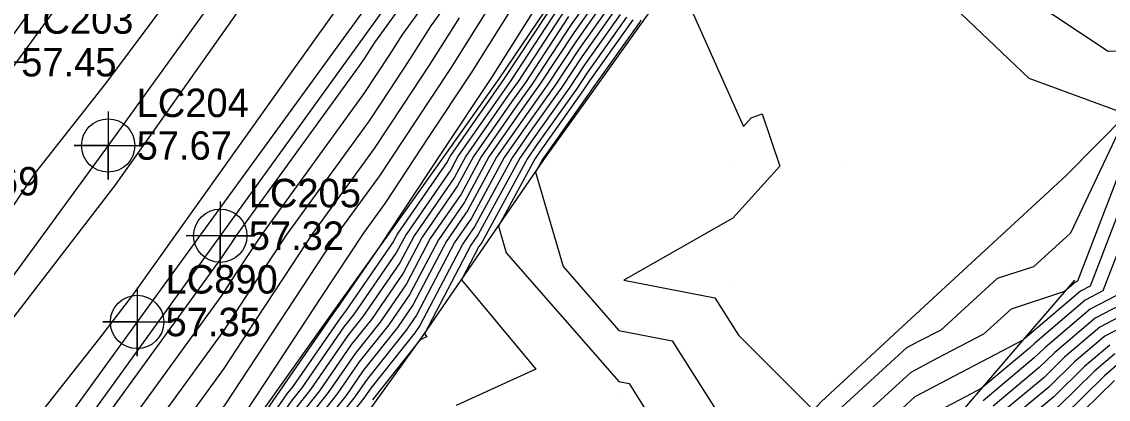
# Model space of a CAD drawing. Extents: x 2188792 to 2191981, y 386090 to 389710.
# Drawn here: x 2190227.7 to 2190323.1, y 387729.7 to 387762.9 of the extents above; entities that cross this region are included whole.
import ezdxf

# ---------------------------------------------------------------- set-up
doc = ezdxf.new("R2010")
doc.units = 0
for name, color, linetype in [('DTM Contours Major', 7, 'Continuous'), ('DTM Contours Minor', 7, 'Continuous'), ('Exist DTM QL2 LIDAR Elevation Point', 7, 'Continuous'), ('Exist Roads EOP', 7, 'Continuous'), ('Exist Roads EOP Cogo Elevation', 7, 'Continuous'), ('Exist Roads EOP Cogo Number', 7, 'Continuous'), ('Exist Roads EOP Cogo Point CELL', 7, 'Continuous'), ('Exist Roads EOT', 7, 'Continuous'), ('Exist Roads EOT Cogo Elevation', 7, 'Continuous'), ('Exist Roads EOT Cogo Number', 7, 'Continuous'), ('Exist Roads EOT Cogo Point CELL', 7, 'Continuous'), ('PH Exist DTM Breakline', 7, 'Continuous')]:
    doc.layers.add(name, color=color, linetype=linetype)

msp = doc.modelspace()

# ---------------------------------------------------------------- linework, layer by layer
at = {"layer": 'DTM Contours Major'}
for points in [[(2190218.456, 387701.786), (2190227.964, 387714.893), (2190229.45, 387716.967), (2190230.892, 387718.979), (2190232.292, 387720.934), (2190245.286, 387738.846), (2190246.51, 387740.711), (2190247.67, 387742.479), (2190248.772, 387744.157), (2190257.784, 387756.577), (2190258.921, 387758.299), (2190260.004, 387759.938), (2190261.168, 387761.785), (2190274.661, 387780.393)], [(2190307.217, 387766.453), (2190316.134, 387757.911), (2190324.761, 387754.756), (2190319.81, 387744.296), (2190316.542, 387741.341), (2190313.357, 387740.301), (2190308.401, 387735.783), (2190306.457, 387734.761), (2190305.402, 387734.206), (2190299.411, 387728.718)], [(2190273.614, 387765.399), (2190268.942, 387757.989), (2190264.596, 387751.41), (2190260.031, 387744.499), (2190259.974, 387744.419), (2190259.136, 387743.142), (2190255.371, 387737.676), (2190255.314, 387737.604), (2190250.727, 387730.957), (2190250.605, 387730.803), (2190246.088, 387724.269), (2190245.908, 387724.041), (2190240.646, 387716.891), (2190240.388, 387716.558), (2190235.157, 387709.453), (2190234.868, 387709.08), (2190229.666, 387702.018), (2190229.348, 387701.607), (2190224.174, 387694.584)], [(2190277.438, 387764.713), (2190275.953, 387762.619), (2190272.566, 387757.461), (2190271.045, 387755.317), (2190268.058, 387751.015), (2190266.278, 387747.733), (2190263.58, 387743.833), (2190261.496, 387739.855), (2190259.171, 387736.479), (2190257.006, 387733.762), (2190254.62, 387730.304), (2190252.504, 387727.63), (2190250.063, 387724.099), (2190247.992, 387721.466), (2190245.052, 387717.47), (2190242.494, 387714.178), (2190239.504, 387710.117), (2190236.995, 387706.883), (2190233.959, 387702.761), (2190231.494, 387699.58), (2190228.416, 387695.401), (2190225.994, 387692.271)], [(2190280.252, 387763.524), (2190277.109, 387759.091), (2190275.766, 387757.046), (2190272.603, 387752.586), (2190271.427, 387750.893), (2190267.794, 387744.19), (2190267.137, 387743.242), (2190263.055, 387735.449), (2190263.267, 387735.195), (2190263.041, 387735.091), (2190262.644, 387734.871), (2190258.699, 387729.92), (2190258.513, 387729.65)], [(2190324.892, 387738.359), (2190321.961, 387736.832), (2190318.412, 387733.813), (2190317.049, 387732.476), (2190313.019, 387729.104)], [(2190324.111, 387732.888), (2190322.78, 387731.756), (2190319.174, 387728.221), (2190317.482, 387726.805), (2190314.246, 387723.658), (2190312.152, 387721.939), (2190309.328, 387719.218), (2190307.187, 387716.235), (2190304.187, 387712.287), (2190302.104, 387709.386), (2190299.023, 387705.335), (2190296.998, 387702.517), (2190296.445, 387700.171), (2190293.815, 387695.062), (2190291.908, 387692.794), (2190289.248, 387687.115), (2190288.634, 387685.669), (2190285.479, 387681.106), (2190282.146, 387676.285), (2190281.697, 387675.341), (2190278.212, 387670.363), (2190277.906, 387669.746), (2190273.071, 387663.513)]]:
    msp.add_lwpolyline(points, dxfattribs=at)
at = {"layer": 'DTM Contours Minor'}
for points in [[(2190274.614, 387783.039), (2190258.679, 387761.062), (2190258.216, 387760.328), (2190257.786, 387759.677), (2190257.334, 387758.992), (2190246.531, 387744.104), (2190246.108, 387743.459), (2190245.662, 387742.78), (2190245.192, 387742.064), (2190229.327, 387720.193), (2190228.805, 387719.465), (2190228.268, 387718.715), (2190227.714, 387717.942), (2190215.973, 387701.758)], [(2190219.575, 387716.076), (2190234.549, 387735.079), (2190237.443, 387738.838), (2190249.235, 387755.366), (2190251.15, 387758.09), (2190265.367, 387778.02)], [(2190220.939, 387701.815), (2190228.214, 387711.844), (2190230.632, 387715.219), (2190232.978, 387718.494), (2190235.256, 387721.674), (2190245.379, 387735.629), (2190247.357, 387738.642), (2190249.232, 387741.498), (2190251.012, 387744.209), (2190258.233, 387754.161), (2190260.056, 387756.921), (2190261.792, 387759.549), (2190263.657, 387762.508), (2190274.708, 387777.747)], [(2190243.271, 387768.482), (2190235.055, 387757.448), (2190228.888, 387749.601), (2190217.395, 387732.559), (2190214.432, 387727.547), (2190204.397, 387712.818), (2190202.052, 387708.946), (2190187.254, 387685.834), (2190204.7, 387708.079), (2190206.378, 387710.213), (2190218.002, 387725.342), (2190221.117, 387729.294), (2190235.868, 387748.461), (2190239.037, 387752.903), (2190247.964, 387765.605)], [(2190313.388, 387766.775), (2190323.109, 387760.3), (2190329.813, 387760.503)], [(2190275.029, 387765.442), (2190270.006, 387757.793), (2190269.799, 387757.501), (2190265.363, 387751.114), (2190265.066, 387750.567), (2190260.734, 387744.307), (2190260.328, 387743.532), (2190256.131, 387737.437), (2190255.652, 387736.836), (2190251.505, 387730.826), (2190250.985, 387730.169), (2190246.883, 387724.235), (2190246.325, 387723.526), (2190241.527, 387717.007), (2190240.809, 387716.082), (2190236.026, 387709.586), (2190235.293, 387708.641), (2190230.525, 387702.166), (2190229.777, 387701.202), (2190225.022, 387694.748)], [(2190271.125, 387764.676), (2190267.154, 387758.379), (2190263.461, 387752.788), (2190259.582, 387746.914), (2190257.733, 387744.367), (2190253.919, 387738.556), (2190249.9, 387732.434), (2190245.661, 387725.977), (2190244.151, 387723.895), (2190239.238, 387717.038), (2190234.179, 387709.975), (2190228.965, 387702.697), (2190228.387, 387701.9), (2190223.206, 387694.664)], [(2190275.26, 387764.736), (2190270.646, 387757.71), (2190270.111, 387756.955), (2190266.037, 387751.089), (2190265.369, 387749.858), (2190261.446, 387744.188), (2190260.62, 387742.612), (2190256.891, 387737.198), (2190255.991, 387736.067), (2190252.284, 387730.696), (2190251.365, 387729.534), (2190247.678, 387724.201), (2190246.742, 387723.011), (2190242.409, 387717.123), (2190241.23, 387715.606), (2190236.896, 387709.719), (2190235.718, 387708.201), (2190231.383, 387702.315), (2190230.207, 387700.796), (2190225.87, 387694.911)], [(2190225.904, 387701.872), (2190228.715, 387705.746), (2190232.996, 387711.723), (2190237.152, 387717.523), (2190241.186, 387723.155), (2190245.567, 387729.195), (2190249.053, 387734.504), (2190252.356, 387739.537), (2190255.493, 387744.314), (2190259.132, 387749.33), (2190262.326, 387754.166), (2190265.367, 387758.769), (2190268.636, 387763.953)], [(2190278.001, 387764.475), (2190276.184, 387761.914), (2190273.206, 387757.378), (2190271.357, 387754.77), (2190268.732, 387750.991), (2190266.581, 387747.024), (2190264.292, 387743.715), (2190261.788, 387738.936), (2190259.931, 387736.24), (2190257.345, 387732.993), (2190255.398, 387730.173), (2190252.884, 387726.996), (2190250.858, 387724.065), (2190248.409, 387720.951), (2190245.933, 387717.586), (2190242.915, 387713.703), (2190240.373, 387710.25), (2190237.42, 387706.443), (2190234.817, 387702.909), (2190231.924, 387699.175), (2190229.264, 387695.565), (2190226.426, 387691.898)], [(2190275.491, 387764.031), (2190271.286, 387757.627), (2190270.422, 387756.409), (2190266.71, 387751.064), (2190265.672, 387749.15), (2190262.157, 387744.07), (2190260.912, 387741.693), (2190257.651, 387736.958), (2190256.329, 387735.299), (2190253.063, 387730.565), (2190251.745, 387728.899), (2190248.473, 387724.167), (2190247.159, 387722.496), (2190243.29, 387717.238), (2190241.651, 387715.13), (2190237.765, 387709.852), (2190236.144, 387707.762), (2190232.242, 387702.464), (2190230.636, 387700.391), (2190226.719, 387695.074)], [(2190278.563, 387764.238), (2190276.415, 387761.208), (2190273.846, 387757.295), (2190271.668, 387754.224), (2190269.406, 387750.966), (2190266.884, 387746.316), (2190265.003, 387743.597), (2190262.08, 387738.017), (2190260.691, 387736.001), (2190257.683, 387732.225), (2190256.177, 387730.042), (2190253.264, 387726.361), (2190251.653, 387724.031), (2190248.826, 387720.436), (2190246.814, 387717.702), (2190243.337, 387713.227), (2190241.243, 387710.383), (2190237.845, 387706.004), (2190235.676, 387703.058), (2190232.353, 387698.769), (2190230.112, 387695.728), (2190226.859, 387691.524)], [(2190279.126, 387764), (2190276.647, 387760.502), (2190274.486, 387757.212), (2190271.98, 387753.678), (2190270.079, 387750.942), (2190267.187, 387745.607), (2190265.714, 387743.478), (2190262.372, 387737.098), (2190261.451, 387735.761), (2190258.022, 387731.457), (2190256.955, 387729.912), (2190253.644, 387725.726), (2190252.448, 387723.997), (2190249.243, 387719.921), (2190247.695, 387717.818), (2190243.758, 387712.751), (2190242.112, 387710.516), (2190238.271, 387705.565), (2190236.534, 387703.207), (2190232.782, 387698.364), (2190230.961, 387695.892), (2190227.292, 387691.151)], [(2190286.269, 387764.431), (2190291.097, 387753.657), (2190291.745, 387754.421), (2190292.721, 387754.795), (2190294.267, 387750.176), (2190290.135, 387745.602), (2190280.562, 387740.175), (2190288.576, 387738.616), (2190290.659, 387735.329), (2190297.218, 387728.728)], [(2190223.421, 387701.843), (2190228.465, 387708.795), (2190231.814, 387713.471), (2190235.065, 387718.009), (2190238.221, 387722.414), (2190245.473, 387732.412), (2190248.205, 387736.573), (2190250.794, 387740.517), (2190253.252, 387744.262), (2190258.683, 387751.746), (2190261.191, 387755.543), (2190263.579, 387759.159), (2190266.146, 387763.23)], [(2190279.689, 387763.762), (2190276.878, 387759.797), (2190275.126, 387757.129), (2190272.292, 387753.132), (2190270.753, 387750.917), (2190267.491, 387744.899), (2190266.426, 387743.36), (2190262.664, 387736.179), (2190262.211, 387735.522), (2190258.36, 387730.688), (2190257.734, 387729.781), (2190254.024, 387725.092), (2190253.244, 387723.963), (2190249.66, 387719.406), (2190248.576, 387717.934), (2190244.179, 387712.275), (2190242.982, 387710.648), (2190238.696, 387705.125), (2190237.393, 387703.355), (2190233.212, 387697.959), (2190231.809, 387696.055), (2190227.725, 387690.777), (2190226.112, 387688.75)], [(2190275.722, 387763.325), (2190271.926, 387757.544), (2190270.734, 387755.863), (2190267.384, 387751.04), (2190265.975, 387748.441), (2190262.869, 387743.952), (2190261.204, 387740.774), (2190258.411, 387736.719), (2190256.668, 387734.53), (2190253.841, 387730.434), (2190252.124, 387728.265), (2190249.268, 387724.133), (2190247.576, 387721.981), (2190244.171, 387717.354), (2190242.073, 387714.654), (2190238.635, 387709.984), (2190236.569, 387707.322), (2190233.1, 387702.612), (2190231.065, 387699.986), (2190227.567, 387695.238)], [(2190280.815, 387763.286), (2190277.34, 387758.385), (2190276.406, 387756.963), (2190272.915, 387752.04), (2190272.101, 387750.868), (2190268.097, 387743.482), (2190267.849, 387743.124), (2190266.308, 387740.182), (2190272.843, 387732.345), (2190265.864, 387729.154)], [(2190281.378, 387763.048), (2190277.571, 387757.68), (2190277.046, 387756.88), (2190273.226, 387751.494), (2190272.775, 387750.844), (2190269.56, 387744.914), (2190270.244, 387742.575), (2190280.134, 387731.248), (2190281.034, 387731.073), (2190282.509, 387728.746)], [(2190282.074, 387763.013), (2190281.941, 387762.81), (2190277.802, 387756.974), (2190277.686, 387756.797), (2190273.538, 387750.948), (2190273.448, 387750.819), (2190272.813, 387749.646), (2190275.235, 387741.364), (2190280.134, 387735.753), (2190284.805, 387734.845), (2190291.926, 387723.608)], [(2190325.437, 387753.156), (2190320.405, 387740.073), (2190320.24, 387739.987), (2190319.267, 387739.158), (2190314.581, 387737.63), (2190312.152, 387735.416), (2190308.014, 387733.239), (2190305.768, 387732.057), (2190301.151, 387727.828)], [(2190326.102, 387751.541), (2190321.527, 387739.644), (2190320.67, 387739.198), (2190315.791, 387735.047), (2190315.774, 387735.029), (2190315.614, 387734.896), (2190309.57, 387731.717), (2190306.133, 387729.908), (2190302.891, 387726.938)], [(2190326.767, 387749.926), (2190322.649, 387739.216), (2190321.101, 387738.409), (2190316.665, 387734.635), (2190316.199, 387734.178), (2190311.962, 387730.634), (2190311.127, 387730.194), (2190306.499, 387727.76)], [(2190323.77, 387738.787), (2190321.531, 387737.621), (2190317.539, 387734.224), (2190316.624, 387733.327), (2190312.126, 387729.564)], [(2190326.013, 387737.93), (2190322.391, 387736.043), (2190319.286, 387733.401), (2190317.474, 387731.625), (2190313.912, 387728.645), (2190312.568, 387727.338), (2190308.495, 387723.995), (2190307.674, 387723.204), (2190303.77, 387717.763), (2190302.863, 387716.57), (2190298.999, 387711.189), (2190298.034, 387709.92), (2190294.211, 387704.6), (2190293.167, 387700.171), (2190291.904, 387697.716), (2190287.551, 387692.539), (2190286.416, 387690.117), (2190284.384, 387685.334), (2190282.711, 387682.914), (2190280.943, 387680.357), (2190278.978, 387676.224), (2190276.879, 387673.226), (2190275.226, 387669.892), (2190270.133, 387663.326)], [(2190327.135, 387737.501), (2190322.821, 387735.254), (2190320.159, 387732.99), (2190317.899, 387730.774), (2190314.804, 387728.185), (2190312.988, 387726.418), (2190309.41, 387723.481), (2190308.088, 387722.207), (2190304.624, 387717.381), (2190303.194, 387715.499), (2190299.775, 387710.738), (2190298.281, 387708.774), (2190294.908, 387704.079), (2190293.987, 387700.171), (2190292.382, 387697.053), (2190288.64, 387692.603), (2190287.124, 387689.366), (2190285.446, 387685.418), (2190283.403, 387682.462), (2190281.243, 387679.339), (2190279.658, 387676.004), (2190277.212, 387672.51), (2190275.896, 387669.855), (2190270.133, 387662.426)], [(2190323.251, 387734.466), (2190321.033, 387732.578), (2190318.324, 387729.923), (2190315.697, 387727.725), (2190313.407, 387725.498), (2190310.324, 387722.967), (2190308.501, 387721.211), (2190305.479, 387716.999), (2190303.525, 387714.428), (2190300.551, 387710.287), (2190298.528, 387707.627), (2190295.605, 387703.558), (2190294.806, 387700.171), (2190292.86, 387696.389), (2190289.729, 387692.667), (2190287.832, 387688.616), (2190286.509, 387685.502), (2190284.095, 387682.01), (2190281.544, 387678.321), (2190280.338, 387675.783), (2190277.546, 387671.794), (2190276.566, 387669.819), (2190270.133, 387661.526)], [(2190323.681, 387733.677), (2190321.907, 387732.167), (2190318.749, 387729.072), (2190316.59, 387727.265), (2190313.827, 387724.578), (2190311.238, 387722.453), (2190308.915, 387720.214), (2190306.333, 387716.617), (2190303.856, 387713.357), (2190301.327, 387709.836), (2190298.776, 387706.481), (2190296.301, 387703.038), (2190295.626, 387700.171), (2190293.337, 387695.726), (2190290.819, 387692.73), (2190288.54, 387687.866), (2190287.571, 387685.586), (2190284.787, 387681.558), (2190281.845, 387677.303), (2190281.018, 387675.562), (2190277.879, 387671.079), (2190277.236, 387669.782), (2190270.133, 387660.626)], [(2190323.654, 387731.344), (2190319.599, 387727.37), (2190318.375, 387726.345), (2190314.666, 387722.738), (2190313.066, 387721.425), (2190309.741, 387718.221), (2190308.042, 387715.853), (2190304.518, 387711.216), (2190302.88, 387708.935), (2190299.27, 387704.188), (2190297.695, 387701.996), (2190297.265, 387700.171), (2190294.293, 387694.399), (2190292.998, 387692.858), (2190289.956, 387686.365), (2190289.696, 387685.753), (2190286.172, 387680.655), (2190282.447, 387675.267), (2190282.377, 387675.121), (2190279.838, 387671.494), (2190278.591, 387669.731), (2190278.544, 387669.67), (2190271.488, 387660.607)]]:
    msp.add_lwpolyline(points, dxfattribs=at)
at = {"layer": 'Exist DTM QL2 LIDAR Elevation Point'}
for p, q in [((2190290.135, 387750.176), (2190290.135, 387750.176)), ((2190300.136, 387750.176), (2190300.136, 387750.176)), ((2190280.134, 387740.175), (2190280.134, 387740.175)), ((2190290.135, 387740.175), (2190290.135, 387740.175)), ((2190280.134, 387730.174), (2190280.134, 387730.174))]:
    msp.add_line(p, q, dxfattribs=at)
at = {"layer": 'Exist Roads EOP'}
for points in [[(2190313.986, 387884.141), (2190285.547, 387843.636), (2190254.588, 387800.045), (2190225.155, 387759.32), (2190194.829, 387717.425), (2190164.291, 387675.101), (2190137.229, 387637.301), (2190105.098, 387592.774), (2190071.411, 387546.221), (2190039.296, 387501.568), (2190007.542, 387457.958), (2189976.844, 387415.407), (2189936.359, 387359.145), (2189907.138, 387318.716), (2189868.636, 387265.243), (2189836.428, 387220.463), (2189805.695, 387177.815), (2189775.592, 387135.957), (2189745.498, 387094.055), (2189715.496, 387052.249), (2189683.869, 387008.07), (2189653.218, 386965.867), (2189623.729, 386924.667)], [(2190335.128, 387868.989), (2190306.373, 387829.271), (2190274.581, 387784.921), (2190245.133, 387744.071), (2190214.553, 387701.741), (2190184.89, 387660.475), (2190157.493, 387622.204), (2190126.048, 387578.501), (2190091.216, 387530.568), (2190059.634, 387486.726), (2190026.932, 387441.783), (2189997.689, 387401.032), (2189957.023, 387344.154), (2189927.908, 387303.922), (2189889.008, 387250.224), (2189856.606, 387205.5), (2189825.68, 387162.612), (2189795.668, 387120.822), (2189765.955, 387079.619), (2189734.998, 387036.704), (2189703.849, 386993.356), (2189673.984, 386951.979), (2189643.253, 386909.427)]]:
    msp.add_lwpolyline(points, dxfattribs=at)
at = {"layer": 'Exist Roads EOP Cogo Point CELL'}
for points in [[(2190225.155, 387762.32), (2190225.155, 387756.32), (2190225.155, 387759.32), (2190228.155, 387759.32), (2190222.155, 387759.32)], [(2190245.133, 387747.071), (2190245.133, 387741.071), (2190245.133, 387744.071), (2190248.133, 387744.071), (2190242.133, 387744.071)]]:
    msp.add_lwpolyline(points, dxfattribs=at)
msp.add_circle((2190245.133, 387744.071), 2.344, dxfattribs=at)
at = {"layer": 'Exist Roads EOT'}
for points in [[(2189910.407, 387320.236), (2189942.075, 387364.22), (2189970.438, 387403.768), (2190000.916, 387446.161), (2190032.053, 387489.248), (2190063.107, 387532.142), (2190093.978, 387574.79), (2190125.104, 387617.946), (2190155.102, 387659.638), (2190185.949, 387702.484), (2190216.886, 387745.11), (2190247.602, 387787.3), (2190276.876, 387828.015), (2190303.928, 387865.67), (2190323.039, 387892.195)], [(2190333.162, 387868.755), (2190301.785, 387825.12), (2190269.645, 387780.315), (2190237.827, 387736.49), (2190205.816, 387692.275), (2190173.845, 387647.822), (2190143.211, 387605.324), (2190112.772, 387563.076), (2190082.117, 387520.492), (2190050.947, 387477.405), (2190019.959, 387434.524), (2189989.253, 387391.986)], [(2190295.87, 387836.508), (2190264.435, 387792.457), (2190235.289, 387751.997), (2190204.567, 387709.955), (2190174.375, 387667.889)]]:
    msp.add_lwpolyline(points, dxfattribs=at)
at = {"layer": 'Exist Roads EOT Cogo Point CELL'}
for points in [[(2190235.289, 387754.997), (2190235.289, 387748.997), (2190235.289, 387751.997), (2190232.289, 387751.997), (2190238.289, 387751.997)], [(2190237.827, 387739.49), (2190237.827, 387733.49), (2190237.827, 387736.49), (2190234.827, 387736.49), (2190240.827, 387736.49)]]:
    msp.add_lwpolyline(points, dxfattribs=at)
for centre in [(2190235.289, 387751.997), (2190237.827, 387736.49)]:
    msp.add_circle(centre, 2.344, dxfattribs=at)
at = {"layer": 'PH Exist DTM Breakline'}
for points in [[(2190177.189, 387623.277), (2190182.728, 387630.176), (2190188.266, 387637.075), (2190193.805, 387643.974), (2190199.215, 387651.571), (2190204.625, 387659.167), (2190210.035, 387666.763), (2190216.463, 387674.309), (2190222.892, 387681.855), (2190229.32, 387689.401), (2190234.648, 387696.602), (2190239.977, 387703.803), (2190245.305, 387711.003), (2190250.633, 387718.204), (2190254.737, 387723.9), (2190258.842, 387729.595), (2190262.946, 387735.291), (2190268.28, 387743.052), (2190273.615, 387750.813), (2190277.868, 387756.773), (2190282.122, 387762.734), (2190286.375, 387768.694), (2190289.591, 387773.066)], [(2190274.919, 387765.778), (2190269.603, 387757.845), (2190264.824, 387751.133), (2190260.046, 387744.421), (2190255.267, 387737.709), (2190250.489, 387730.997), (2190245.711, 387724.285), (2190240.15, 387716.826), (2190234.59, 387709.367), (2190229.03, 387701.908), (2190223.47, 387694.449), (2190217.658, 387687.036), (2190211.846, 387679.623), (2190206.034, 387672.21), (2190200.222, 387664.797), (2190194.726, 387657.469), (2190189.23, 387650.141), (2190183.735, 387642.813), (2190178.239, 387635.484), (2190172.743, 387628.156)], [(2190330.139, 387760.177), (2190324.773, 387754.768), (2190319.407, 387749.36), (2190312.243, 387742.734), (2190305.078, 387736.109), (2190297.914, 387729.484), (2190291.987, 387723.046), (2190286.061, 387716.609), (2190280.134, 387710.172), (2190274.846, 387704.123), (2190269.558, 387698.073), (2190264.271, 387692.024), (2190259.056, 387685.954), (2190253.842, 387679.884), (2190248.627, 387673.815), (2190243.413, 387667.745), (2190238.198, 387661.675), (2190232.175, 387654.505), (2190226.152, 387647.335)], [(2190320.138, 387740.175), (2190315.757, 387735.063), (2190311.377, 387729.95), (2190306.996, 387724.838), (2190302.29, 387718.424), (2190297.583, 387712.011), (2190292.877, 387705.597), (2190290.135, 387700.171), (2190284.309, 387692.35), (2190279.583, 387684.956), (2190274.858, 387677.562), (2190270.133, 387670.168), (2190265.825, 387664.933), (2190261.516, 387659.698), (2190257.208, 387654.463), (2190251.355, 387647.911), (2190245.502, 387641.358), (2190239.65, 387634.806), (2190233.797, 387628.254), (2190227.945, 387621.701), (2190223.415, 387613.536)]]:
    msp.add_lwpolyline(points, dxfattribs=at)

# ---------------------------------------------------------------- texts
at = {"layer": 'Exist Roads EOP Cogo Elevation'}
for s, p in [('57.45', (2190227.655, 387758.07)), ('57.32', (2190247.633, 387742.821))]:
    msp.add_text(s, height=2.5, dxfattribs=at).set_placement(p)
at = {"layer": 'Exist Roads EOP Cogo Number'}
for s, p in [('LC203', (2190227.655, 387761.82)), ('LC205', (2190247.633, 387746.571))]:
    msp.add_text(s, height=2.5, dxfattribs=at).set_placement(p)
at = {"layer": 'Exist Roads EOT Cogo Elevation'}
for s, p in [('57.67', (2190237.789, 387750.747)), ('57.35', (2190240.327, 387735.24))]:
    msp.add_text(s, height=2.5, dxfattribs=at).set_placement(p)
at = {"layer": 'Exist Roads EOT Cogo Number'}
for s, p in [('LC204', (2190237.789, 387754.497)), ('LC869', (2190219.386, 387747.61)), ('LC890', (2190240.327, 387738.99))]:
    msp.add_text(s, height=2.5, dxfattribs=at).set_placement(p)

doc.saveas('drawing.dxf')
